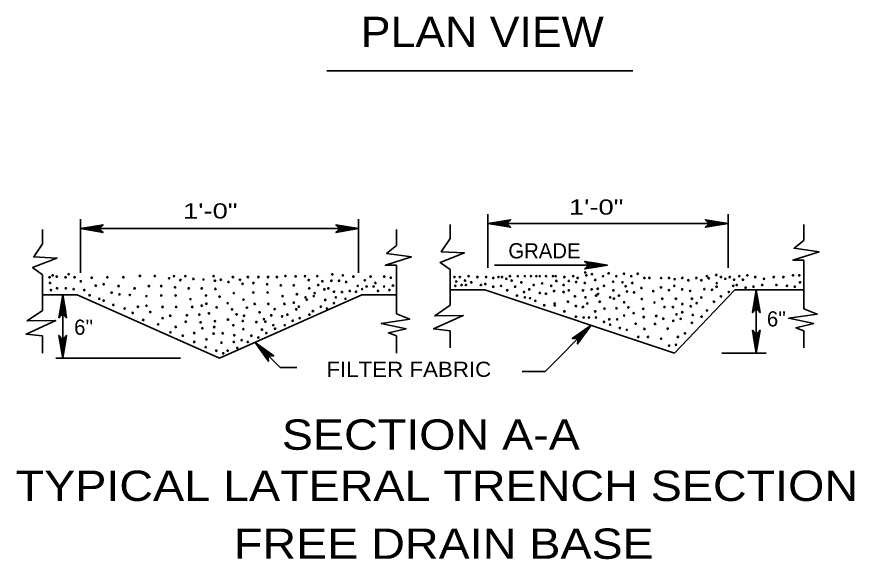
# Model space of a CAD drawing. Extents: x -48732 to -48696.6, y -117659.8 to -117637.8.
# Drawn here: x -48715.46 to -48708.83, y -117648.28 to -117643.99 of the extents above; entities that cross this region are included whole.
import ezdxf

# ---------------------------------------------------------------- set-up
doc = ezdxf.new("R2010")
doc.units = 0
doc.header["$LTSCALE"] = 0.048
doc.layers.add('3', color=7, linetype='Continuous', lineweight=35)

msp = doc.modelspace()

# ---------------------------------------------------------------- linework, layer by layer
at = {"layer": '3'}
for p, q in [((-48713.00633, -117644.41467), (-48710.58575, -117644.41467)), ((-48714.95692, -117646.01342), (-48714.95692, -117645.58742)), ((-48712.75492, -117646.01342), (-48712.75492, -117645.58742)), ((-48711.73225, -117645.97275), (-48711.73225, -117645.54675)), ((-48709.83125, -117645.97275), (-48709.83125, -117645.54675)), ((-48712.03125, -117645.74175), (-48712.03125, -117645.62975)), ((-48711.73225, -117645.62175), (-48709.83125, -117645.62175)), ((-48709.23125, -117645.75575), (-48709.23125, -117645.62975)), ((-48715.25592, -117645.78242), (-48715.25592, -117645.67042)), ((-48714.95692, -117645.66242), (-48712.75492, -117645.66242)), ((-48712.45592, -117645.79642), (-48712.45592, -117645.67042)), ((-48709.23125, -117646.29675), (-48709.23125, -117645.91175)), ((-48712.45592, -117646.33742), (-48712.45592, -117645.95242)), ((-48712.03125, -117646.26875), (-48712.03125, -117645.98675)), ((-48711.68025, -117645.95175), (-48710.78625, -117645.95175)), ((-48715.25592, -117646.30942), (-48715.25592, -117646.02742)), ((-48712.03125, -117646.14675), (-48711.75725, -117646.14675)), ((-48711.75725, -117646.14675), (-48710.25625, -117646.64675)), ((-48710.25625, -117646.64675), (-48709.77925, -117646.14675)), ((-48709.50525, -117646.14675), (-48709.77925, -117646.14675)), ((-48709.63025, -117646.28175), (-48709.60825, -117646.14675)), ((-48709.60825, -117646.14675), (-48709.58525, -117646.28175)), ((-48709.60825, -117646.64675), (-48709.60825, -117646.14675)), ((-48709.23125, -117646.14675), (-48709.50525, -117646.14675)), ((-48715.25592, -117646.18742), (-48714.98192, -117646.18742)), ((-48715.11792, -117646.32242), (-48715.09592, -117646.18742)), ((-48715.09592, -117646.68742), (-48715.09592, -117646.18742)), ((-48715.09592, -117646.18742), (-48715.07292, -117646.32242)), ((-48714.98192, -117646.18742), (-48713.85592, -117646.68742)), ((-48712.72992, -117646.18742), (-48713.85592, -117646.68742)), ((-48712.45592, -117646.18742), (-48712.72992, -117646.18742)), ((-48709.58525, -117646.28175), (-48709.63025, -117646.28175)), ((-48715.07292, -117646.32242), (-48715.11792, -117646.32242)), ((-48710.98125, -117646.47275), (-48710.91625, -117646.42675)), ((-48710.91625, -117646.42675), (-48710.96225, -117646.49175)), ((-48715.25592, -117646.64742), (-48715.25592, -117646.51142)), ((-48712.45592, -117646.64742), (-48712.45592, -117646.51142)), ((-48712.03125, -117646.60675), (-48712.03125, -117646.47075)), ((-48710.96225, -117646.49175), (-48710.98125, -117646.47275)), ((-48709.23125, -117646.60675), (-48709.23125, -117646.47075)), ((-48715.09592, -117646.68742), (-48715.11692, -117646.55942)), ((-48715.11692, -117646.55942), (-48715.07492, -117646.55942)), ((-48715.07492, -117646.55942), (-48715.09592, -117646.68742)), ((-48713.37592, -117646.76142), (-48713.57492, -117646.56442)), ((-48709.60825, -117646.64675), (-48709.62925, -117646.51875)), ((-48709.62925, -117646.51875), (-48709.58725, -117646.51875)), ((-48709.58725, -117646.51875), (-48709.60825, -117646.64675)), ((-48709.88125, -117646.64675), (-48709.53025, -117646.64675)), ((-48715.15192, -117646.68742), (-48714.16492, -117646.68742)), ((-48713.37592, -117646.76142), (-48713.24392, -117646.76142))]:
    msp.add_line(p, q, dxfattribs=at)
for points in [[(-48714.77692, -117645.63242), (-48714.95692, -117645.66242), (-48714.77692, -117645.69242), (-48714.78192, -117645.68842), (-48714.93892, -117645.66242), (-48714.78092, -117645.63642), (-48714.78592, -117645.64042), (-48714.91992, -117645.66242), (-48714.78592, -117645.68442), (-48714.79092, -117645.68142), (-48714.90192, -117645.66242), (-48714.79092, -117645.64342), (-48714.79492, -117645.64742), (-48714.88392, -117645.66242), (-48714.79492, -117645.67742), (-48714.79992, -117645.67342), (-48714.86592, -117645.66242), (-48714.79992, -117645.65142), (-48714.80392, -117645.65542), (-48714.84692, -117645.66242), (-48714.80392, -117645.66942), (-48714.80892, -117645.66542), (-48714.82892, -117645.66242), (-48714.80892, -117645.65942), (-48714.77692, -117645.63242), (-48714.81292, -117645.66242), (-48714.77692, -117645.69242)], [(-48712.93492, -117645.69242), (-48712.75492, -117645.66242), (-48712.93492, -117645.63242), (-48712.92992, -117645.63642), (-48712.77292, -117645.66242), (-48712.93092, -117645.68842), (-48712.92592, -117645.68442), (-48712.79192, -117645.66242), (-48712.92592, -117645.64042), (-48712.92092, -117645.64342), (-48712.80992, -117645.66242), (-48712.92092, -117645.68142), (-48712.91692, -117645.67742), (-48712.82792, -117645.66242), (-48712.91692, -117645.64742), (-48712.91192, -117645.65142), (-48712.84592, -117645.66242), (-48712.91192, -117645.67342), (-48712.90792, -117645.66942), (-48712.86492, -117645.66242), (-48712.90792, -117645.65542), (-48712.90292, -117645.65942), (-48712.88292, -117645.66242), (-48712.90292, -117645.66542), (-48712.93492, -117645.69242), (-48712.89892, -117645.66242), (-48712.93492, -117645.63242)], [(-48711.55225, -117645.59175), (-48711.73225, -117645.62175), (-48711.55225, -117645.65175), (-48711.55725, -117645.64775), (-48711.71425, -117645.62175), (-48711.55625, -117645.59575), (-48711.56125, -117645.59975), (-48711.69525, -117645.62175), (-48711.56125, -117645.64375), (-48711.56625, -117645.64075), (-48711.67725, -117645.62175), (-48711.56625, -117645.60275), (-48711.57025, -117645.60675), (-48711.65925, -117645.62175), (-48711.57025, -117645.63675), (-48711.57525, -117645.63275), (-48711.64125, -117645.62175), (-48711.57525, -117645.61075), (-48711.57925, -117645.61475), (-48711.62225, -117645.62175), (-48711.57925, -117645.62875), (-48711.58425, -117645.62475), (-48711.60425, -117645.62175), (-48711.58425, -117645.61875), (-48711.55225, -117645.59175), (-48711.58825, -117645.62175), (-48711.55225, -117645.65175)], [(-48710.01125, -117645.65175), (-48709.83125, -117645.62175), (-48710.01125, -117645.59175), (-48710.00625, -117645.59575), (-48709.84925, -117645.62175), (-48710.00725, -117645.64775), (-48710.00225, -117645.64375), (-48709.86825, -117645.62175), (-48710.00225, -117645.59975), (-48709.99725, -117645.60275), (-48709.88625, -117645.62175), (-48709.99725, -117645.64075), (-48709.99325, -117645.63675), (-48709.90425, -117645.62175), (-48709.99325, -117645.60675), (-48709.98825, -117645.61075), (-48709.92225, -117645.62175), (-48709.98825, -117645.63275), (-48709.98425, -117645.62875), (-48709.94125, -117645.62175), (-48709.98425, -117645.61475), (-48709.97925, -117645.61875), (-48709.95925, -117645.62175), (-48709.97925, -117645.62475), (-48710.01125, -117645.65175), (-48709.97525, -117645.62175), (-48710.01125, -117645.59175)], [(-48715.25592, -117645.78242), (-48715.32592, -117645.88642), (-48715.14292, -117645.89542), (-48715.33492, -117645.97042), (-48715.25592, -117646.02742)], [(-48712.03125, -117645.74175), (-48712.10125, -117645.84575), (-48711.91825, -117645.85475), (-48712.11025, -117645.92975), (-48712.03125, -117645.98675)], [(-48709.23125, -117645.75575), (-48709.30925, -117645.81775), (-48709.11225, -117645.84575), (-48709.31825, -117645.91175), (-48709.23125, -117645.91175)], [(-48712.45592, -117645.79642), (-48712.53392, -117645.85842), (-48712.33692, -117645.88642), (-48712.54292, -117645.95242), (-48712.45592, -117645.95242)], [(-48710.96625, -117645.98175), (-48710.78625, -117645.95175), (-48710.96625, -117645.92175), (-48710.96125, -117645.92575), (-48710.80425, -117645.95175), (-48710.96225, -117645.97775), (-48710.95725, -117645.97375), (-48710.82325, -117645.95175), (-48710.95725, -117645.92975), (-48710.95225, -117645.93275), (-48710.84125, -117645.95175), (-48710.95225, -117645.97075), (-48710.94825, -117645.96675), (-48710.85925, -117645.95175), (-48710.94825, -117645.93675), (-48710.94325, -117645.94075), (-48710.87725, -117645.95175), (-48710.94325, -117645.96275), (-48710.93925, -117645.95875), (-48710.89625, -117645.95175), (-48710.93925, -117645.94475), (-48710.93425, -117645.94875), (-48710.91425, -117645.95175), (-48710.93425, -117645.95475), (-48710.96625, -117645.98175), (-48710.93025, -117645.95175), (-48710.96625, -117645.92175)], [(-48709.57825, -117646.32675), (-48709.60825, -117646.14675), (-48709.63825, -117646.32675), (-48709.63425, -117646.32175), (-48709.60825, -117646.16475), (-48709.58225, -117646.32275), (-48709.58625, -117646.31775), (-48709.60825, -117646.18375), (-48709.63025, -117646.31775), (-48709.62725, -117646.31275), (-48709.60825, -117646.20175), (-48709.58925, -117646.31275), (-48709.59325, -117646.30875), (-48709.60825, -117646.21975), (-48709.62325, -117646.30875), (-48709.61925, -117646.30375), (-48709.60825, -117646.23775), (-48709.59725, -117646.30375), (-48709.60125, -117646.29975), (-48709.60825, -117646.25675), (-48709.61525, -117646.29975), (-48709.61125, -117646.29475), (-48709.60825, -117646.27475), (-48709.60525, -117646.29475), (-48709.57825, -117646.32675), (-48709.60825, -117646.29075), (-48709.63825, -117646.32675)], [(-48715.06592, -117646.36742), (-48715.09592, -117646.18742), (-48715.12592, -117646.36742), (-48715.12192, -117646.36242), (-48715.09592, -117646.20542), (-48715.06992, -117646.36342), (-48715.07392, -117646.35842), (-48715.09592, -117646.22442), (-48715.11792, -117646.35842), (-48715.11492, -117646.35342), (-48715.09592, -117646.24242), (-48715.07692, -117646.35342), (-48715.08092, -117646.34942), (-48715.09592, -117646.26042), (-48715.11092, -117646.34942), (-48715.10692, -117646.34442), (-48715.09592, -117646.27842), (-48715.08492, -117646.34442), (-48715.08892, -117646.34042), (-48715.09592, -117646.29742), (-48715.10292, -117646.34042), (-48715.09892, -117646.33542), (-48715.09592, -117646.31542), (-48715.09292, -117646.33542), (-48715.06592, -117646.36742), (-48715.09592, -117646.33142), (-48715.12592, -117646.36742)], [(-48715.25592, -117646.30942), (-48715.37792, -117646.39342), (-48715.15192, -117646.38942), (-48715.38692, -117646.49742), (-48715.25592, -117646.51142)], [(-48712.03125, -117646.26875), (-48712.15325, -117646.35275), (-48711.92725, -117646.34875), (-48712.16225, -117646.45675), (-48712.03125, -117646.47075)], [(-48709.23125, -117646.29675), (-48709.12625, -117646.33875), (-48709.35125, -117646.37175), (-48709.15425, -117646.41375), (-48709.29525, -117646.44675), (-48709.23125, -117646.47075)], [(-48712.45592, -117646.33742), (-48712.35092, -117646.37942), (-48712.57592, -117646.41242), (-48712.37892, -117646.45442), (-48712.51992, -117646.48742), (-48712.45592, -117646.51142)], [(-48711.46025, -117646.79375), (-48711.28025, -117646.79375), (-48710.91625, -117646.42675)], [(-48711.02225, -117646.57475), (-48710.91625, -117646.42675), (-48711.06425, -117646.53275), (-48711.05925, -117646.53275), (-48710.92925, -117646.43975), (-48711.02225, -117646.56975), (-48711.02125, -117646.56375), (-48710.94225, -117646.45275), (-48711.05325, -117646.53175), (-48711.04725, -117646.53075), (-48710.95525, -117646.46575), (-48711.02025, -117646.55775), (-48711.02025, -117646.55175), (-48710.96825, -117646.47875), (-48711.04125, -117646.53075), (-48711.03525, -117646.52975), (-48710.98025, -117646.49075), (-48711.01925, -117646.54575), (-48711.01925, -117646.53975), (-48710.99325, -117646.50375), (-48711.02925, -117646.52975), (-48711.02325, -117646.52875), (-48711.00625, -117646.51675), (-48711.01825, -117646.53375), (-48711.02225, -117646.57475), (-48711.01825, -117646.52875), (-48711.06425, -117646.53275)], [(-48715.12592, -117646.50742), (-48715.09592, -117646.68742), (-48715.06592, -117646.50742), (-48715.06992, -117646.51242), (-48715.09592, -117646.66942), (-48715.12192, -117646.51142), (-48715.11792, -117646.51642), (-48715.09592, -117646.65042), (-48715.07392, -117646.51642), (-48715.07692, -117646.52142), (-48715.09592, -117646.63242), (-48715.11492, -117646.52142), (-48715.11092, -117646.52542), (-48715.09592, -117646.61442), (-48715.08092, -117646.52542), (-48715.08492, -117646.53042), (-48715.09592, -117646.59642), (-48715.10692, -117646.53042), (-48715.10292, -117646.53442), (-48715.09592, -117646.57742), (-48715.08892, -117646.53442), (-48715.09292, -117646.53942), (-48715.09592, -117646.55942), (-48715.09892, -117646.53942), (-48715.12592, -117646.50742), (-48715.09592, -117646.54342), (-48715.06592, -117646.50742)], [(-48709.63825, -117646.46675), (-48709.60825, -117646.64675), (-48709.57825, -117646.46675), (-48709.58225, -117646.47175), (-48709.60825, -117646.62875), (-48709.63425, -117646.47075), (-48709.63025, -117646.47575), (-48709.60825, -117646.60975), (-48709.58625, -117646.47575), (-48709.58925, -117646.48075), (-48709.60825, -117646.59175), (-48709.62725, -117646.48075), (-48709.62325, -117646.48475), (-48709.60825, -117646.57375), (-48709.59325, -117646.48475), (-48709.59725, -117646.48975), (-48709.60825, -117646.55575), (-48709.61925, -117646.48975), (-48709.61525, -117646.49375), (-48709.60825, -117646.53675), (-48709.60125, -117646.49375), (-48709.60525, -117646.49875), (-48709.60825, -117646.51875), (-48709.61125, -117646.49875), (-48709.63825, -117646.46675), (-48709.60825, -117646.50275), (-48709.57825, -117646.46675)], [(-48713.42692, -117646.67042), (-48713.57492, -117646.56442), (-48713.46892, -117646.71242), (-48713.46892, -117646.70742), (-48713.56192, -117646.57742), (-48713.43192, -117646.67042), (-48713.43792, -117646.66942), (-48713.54892, -117646.59042), (-48713.46992, -117646.70142), (-48713.47092, -117646.69542), (-48713.53592, -117646.60342), (-48713.44392, -117646.66842), (-48713.44992, -117646.66842), (-48713.52292, -117646.61642), (-48713.47092, -117646.68942), (-48713.47192, -117646.68342), (-48713.51092, -117646.62842), (-48713.45592, -117646.66742), (-48713.46192, -117646.66742), (-48713.49792, -117646.64142), (-48713.47192, -117646.67742), (-48713.47292, -117646.67142), (-48713.48492, -117646.65442), (-48713.46792, -117646.66642), (-48713.42692, -117646.67042), (-48713.47292, -117646.66642), (-48713.46892, -117646.71242)]]:
    msp.add_lwpolyline(points, dxfattribs=at)
msp.add_lwpolyline([(-48710.91025, -117645.97175), (-48710.91025, -117645.93075), (-48710.78625, -117645.95175)], close=True, dxfattribs=at)
for centre in [(-48715.20042, -117646.04692), (-48715.17642, -117646.03192), (-48715.14342, -117646.04192), (-48715.07342, -117646.04692), (-48715.04942, -117646.02292), (-48715.00242, -117646.04692), (-48714.86642, -117646.05092), (-48714.74342, -117646.04692), (-48714.61642, -117646.04692), (-48714.48542, -117646.03692), (-48714.36742, -117646.03692), (-48714.25442, -117646.05592), (-48714.21567, -117646.03892), (-48714.12525, -117646.03892), (-48713.90258, -117646.03892), (-48713.7495, -117646.04583), (-48713.63125, -117646.04583), (-48713.54775, -117646.04583), (-48713.47117, -117646.04583), (-48713.40167, -117646.04583), (-48713.33342, -117646.03692), (-48713.25342, -117646.04092), (-48713.179, -117646.03892), (-48713.08158, -117646.03892), (-48712.96333, -117646.025), (-48712.87983, -117646.03192), (-48712.79642, -117646.04192), (-48712.66042, -117646.04192), (-48712.55242, -117646.04192), (-48712.50042, -117646.05092), (-48711.99617, -117646.04583), (-48711.95442, -117646.04583), (-48711.88483, -117646.03892), (-48711.81525, -117646.04583), (-48711.74575, -117646.04583), (-48711.69008, -117646.05283), (-48711.64833, -117646.04583), (-48711.6205, -117646.04583), (-48711.55783, -117646.03892), (-48711.49525, -117646.03892), (-48711.43958, -117646.03892), (-48711.39083, -117646.03892), (-48711.34908, -117646.03892), (-48711.32133, -117646.03892), (-48711.27258, -117646.03892), (-48711.21692, -117646.03892), (-48711.19608, -117646.03892), (-48711.1265, -117646.04583), (-48711.05692, -117646.03892), (-48711.02208, -117646.05283), (-48710.96158, -117646.00942), (-48710.9525, -117646.03192), (-48710.90892, -117646.02258), (-48710.82033, -117646.03892), (-48710.77717, -117646.016), (-48710.716, -117646.03892), (-48710.65533, -117646.01933), (-48710.59767, -117646.03892), (-48710.54667, -117646.01933), (-48710.49333, -117646.05283), (-48710.45442, -117646.05225), (-48710.36117, -117646.05283), (-48710.2985, -117646.05283), (-48710.19417, -117646.05283), (-48710.08283, -117646.05283), (-48709.99933, -117646.03892), (-48709.98475, -117646.05525), (-48709.92475, -117646.02925), (-48709.888, -117646.04583), (-48709.81842, -117646.04583), (-48709.74192, -117646.03892), (-48709.67925, -117646.03192), (-48709.61667, -117646.04583), (-48709.47058, -117646.04583), (-48709.394, -117646.04583), (-48709.3175, -117646.03192), (-48709.26875, -117646.03192), (-48715.19683, -117646.0925), (-48714.95333, -117646.07858), (-48714.83508, -117646.11342), (-48714.77242, -117646.10292), (-48714.65442, -117646.11692), (-48714.41442, -117646.11692), (-48714.31642, -117646.11692), (-48714.16542, -117646.06992), (-48714.06242, -117646.06092), (-48713.98242, -117646.06492), (-48713.89242, -117646.07492), (-48713.8455, -117646.06675), (-48713.78442, -117646.08392), (-48713.69383, -117646.06675), (-48713.67317, -117646.0995), (-48713.58742, -117646.09292), (-48713.47842, -117646.10292), (-48713.37042, -117646.11192), (-48713.26742, -117646.11192), (-48713.14942, -117646.06992), (-48713.07458, -117646.1085), (-48713.04142, -117646.07892), (-48712.97042, -117646.07492), (-48712.90942, -117646.07492), (-48712.85342, -117646.08392), (-48712.7615, -117646.11542), (-48712.706, -117646.07167), (-48712.69208, -117646.12033), (-48712.63642, -117646.12033), (-48712.6225, -117646.0925), (-48712.553, -117646.12033), (-48712.48342, -117646.11342), (-48711.98925, -117646.11542), (-48711.98225, -117646.08067), (-48711.9405, -117646.1085), (-48711.91267, -117646.07367), (-48711.90575, -117646.1085), (-48711.864, -117646.08758), (-48711.78742, -117646.1085), (-48711.75267, -117646.1015), (-48711.69008, -117646.12242), (-48711.62742, -117646.11542), (-48711.58567, -117646.05975), (-48711.54392, -117646.07367), (-48711.51608, -117646.12242), (-48711.46742, -117646.08758), (-48711.37, -117646.1085), (-48711.30275, -117646.09525), (-48711.23083, -117646.11542), (-48711.18975, -117646.07625), (-48711.13342, -117646.1085), (-48711.09175, -117646.07625), (-48711.034, -117646.08517), (-48710.96492, -117646.09175), (-48710.88258, -117646.06875), (-48710.81342, -117646.11542), (-48710.74092, -117646.08192), (-48710.66725, -117646.08758), (-48710.64217, -117646.11817), (-48710.58942, -117646.09175), (-48710.25675, -117646.11542), (-48710.25375, -117646.06225), (-48710.14575, -117646.07125), (-48710.04275, -117646.07125), (-48709.92283, -117646.12242), (-48709.92075, -117646.09425), (-48709.85325, -117646.05975), (-48709.79058, -117646.11542), (-48709.78367, -117646.06675), (-48709.76275, -117646.1085), (-48709.71408, -117646.06675), (-48709.63058, -117646.12242), (-48709.561, -117646.1085), (-48709.54708, -117646.05975), (-48709.44967, -117646.1085), (-48709.36617, -117646.11542), (-48709.30358, -117646.12242), (-48709.26183, -117646.08758), (-48715.18992, -117646.14825), (-48715.14117, -117646.13425), (-48715.07167, -117646.13425), (-48715.009, -117646.14125), (-48714.9255, -117646.14825), (-48714.88375, -117646.19), (-48714.70983, -117646.16908), (-48714.64725, -117646.183), (-48714.56542, -117646.18792), (-48714.52742, -117646.13592), (-48714.31642, -117646.19192), (-48714.20742, -117646.12692), (-48714.20342, -117646.19192), (-48714.09942, -117646.13592), (-48713.99642, -117646.13592), (-48713.96342, -117646.19192), (-48713.88842, -117646.13992), (-48713.74242, -117646.17292), (-48713.58742, -117646.16792), (-48713.47442, -117646.16792), (-48713.24342, -117646.18192), (-48713.14542, -117646.13492), (-48713.10242, -117646.17292), (-48713.02592, -117646.14333), (-48712.99442, -117646.13592), (-48712.94958, -117646.16217), (-48712.88675, -117646.16417), (-48712.82433, -117646.15517), (-48712.77558, -117646.16217), (-48712.72692, -117646.14125), (-48712.60167, -117646.15517), (-48712.51125, -117646.14825), (-48711.57875, -117646.15025), (-48711.50217, -117646.192), (-48711.4465, -117646.16417), (-48711.40475, -117646.14333), (-48711.32133, -117646.17117), (-48711.27258, -117646.17808), (-48711.20875, -117646.15625), (-48711.13342, -117646.16417), (-48711.09175, -117646.15125), (-48710.97875, -117646.15125), (-48710.91075, -117646.14333), (-48710.876, -117646.192), (-48710.86275, -117646.13792), (-48710.86075, -117646.18025), (-48710.73875, -117646.15125), (-48710.69508, -117646.192), (-48710.63075, -117646.16025), (-48710.57575, -117646.16725), (-48710.51775, -117646.13225), (-48710.42375, -117646.15725), (-48710.36275, -117646.12725), (-48710.29975, -117646.14925), (-48710.19475, -117646.14325), (-48710.13175, -117646.15625), (-48710.01875, -117646.14125), (-48709.95875, -117646.14625), (-48709.82542, -117646.16417), (-48709.69317, -117646.12942), (-48714.80725, -117646.21783), (-48714.77242, -117646.23175), (-48714.43342, -117646.19692), (-48714.08542, -117646.22092), (-48713.95942, -117646.25692), (-48713.85542, -117646.20092), (-48713.79142, -117646.25258), (-48713.66617, -117646.22475), (-48713.57742, -117646.25792), (-48713.46942, -117646.25792), (-48713.35642, -117646.19692), (-48713.34242, -117646.25792), (-48713.26742, -117646.24792), (-48713.17542, -117646.20592), (-48713.16525, -117646.22475), (-48713.10958, -117646.19692), (-48713.01892, -117646.22683), (-48712.94958, -117646.25258), (-48712.9355, -117646.20592), (-48712.85908, -117646.21783), (-48711.43958, -117646.20592), (-48711.39783, -117646.21292), (-48711.35608, -117646.23375), (-48711.203, -117646.25467), (-48711.09867, -117646.24075), (-48711.04375, -117646.19825), (-48710.95975, -117646.20525), (-48710.94475, -117646.25525), (-48710.84675, -117646.24125), (-48710.76467, -117646.20592), (-48710.73475, -117646.21625), (-48710.65375, -117646.24525), (-48710.51417, -117646.21983), (-48710.41375, -117646.24725), (-48710.35275, -117646.21725), (-48710.24475, -117646.21725), (-48710.11775, -117646.21725), (-48710.07975, -117646.25225), (-48710.04275, -117646.20725), (-48709.94367, -117646.24075), (-48709.888, -117646.199), (-48714.69592, -117646.26658), (-48714.6055, -117646.29442), (-48714.50108, -117646.2805), (-48714.43342, -117646.27192), (-48714.40367, -117646.32225), (-48714.30642, -117646.28192), (-48714.19842, -117646.28192), (-48714.07142, -117646.28192), (-48713.99642, -117646.27192), (-48713.87842, -117646.28592), (-48713.75667, -117646.30133), (-48713.63842, -117646.28792), (-48713.41842, -117646.29992), (-48713.24875, -117646.30133), (-48713.22783, -117646.2805), (-48713.1165, -117646.31525), (-48713.05392, -117646.2805), (-48713.00525, -117646.29442), (-48711.2865, -117646.26858), (-48711.203, -117646.26858), (-48711.1265, -117646.31733), (-48711.036, -117646.27558), (-48710.98033, -117646.2825), (-48710.883, -117646.31733), (-48710.80975, -117646.29525), (-48710.71475, -117646.29225), (-48710.62075, -117646.28625), (-48710.50275, -117646.29725), (-48710.33475, -117646.28325), (-48710.26775, -117646.28325), (-48710.19417, -117646.32425), (-48710.19375, -117646.25925), (-48710.12675, -117646.27725), (-48709.99933, -117646.31033), (-48714.54283, -117646.32917), (-48714.45933, -117646.38492), (-48714.30625, -117646.37092), (-48714.24542, -117646.35192), (-48714.11342, -117646.34792), (-48714.01542, -117646.34292), (-48713.93942, -117646.33292), (-48713.78942, -117646.38192), (-48713.72042, -117646.34092), (-48713.66142, -117646.35192), (-48713.53842, -117646.32492), (-48713.50342, -117646.37892), (-48713.44642, -117646.34892), (-48713.36008, -117646.357), (-48713.31833, -117646.34308), (-48713.22092, -117646.37092), (-48713.14433, -117646.34308), (-48711.036, -117646.35908), (-48710.97342, -117646.36608), (-48710.93167, -117646.36608), (-48710.876, -117646.36608), (-48710.77167, -117646.38), (-48710.709, -117646.38), (-48710.65375, -117646.35025), (-48710.57775, -117646.33125), (-48710.49875, -117646.36225), (-48710.39975, -117646.35325), (-48710.34475, -117646.37525), (-48710.23975, -117646.34125), (-48710.20675, -117646.37625), (-48710.11067, -117646.34517), (-48710.04108, -117646.35908), (-48714.34108, -117646.41967), (-48714.20192, -117646.44058), (-48714.12342, -117646.39892), (-48714.00542, -117646.40392), (-48713.99142, -117646.45092), (-48713.89742, -117646.44192), (-48713.89242, -117646.39492), (-48713.74642, -117646.42692), (-48713.67142, -117646.39292), (-48713.56342, -117646.40192), (-48713.49225, -117646.39883), (-48713.42967, -117646.42667), (-48713.41575, -117646.4545), (-48713.33917, -117646.42667), (-48713.27658, -117646.39183), (-48710.81342, -117646.40083), (-48710.76467, -117646.42175), (-48710.68817, -117646.44958), (-48710.56292, -117646.41475), (-48710.49333, -117646.4565), (-48710.40975, -117646.41625), (-48710.30975, -117646.45325), (-48710.26575, -117646.39225), (-48710.11758, -117646.40783), (-48714.24367, -117646.48233), (-48714.14625, -117646.51017), (-48714.05583, -117646.48925), (-48713.90242, -117646.49292), (-48713.83042, -117646.49092), (-48713.73842, -117646.50592), (-48713.66742, -117646.45792), (-48713.60358, -117646.51017), (-48713.52008, -117646.46142), (-48713.48525, -117646.48925), (-48710.6325, -117646.4635), (-48710.542, -117646.51917), (-48710.4655, -117646.51917), (-48710.22892, -117646.51917), (-48710.17325, -117646.49133), (-48714.05583, -117646.55892), (-48713.95842, -117646.538), (-48713.84017, -117646.56583), (-48713.74275, -117646.55892), (-48713.68008, -117646.545), (-48713.63142, -117646.55892), (-48713.54792, -117646.52408), (-48710.36117, -117646.53308), (-48710.2985, -117646.58875), (-48710.24283, -117646.58183), (-48713.96533, -117646.60067), (-48713.88183, -117646.6285), (-48713.82625, -117646.64942), (-48713.79142, -117646.6285), (-48713.71492, -117646.60758)]:
    msp.add_circle(centre, 0.00515, dxfattribs=at)

# ---------------------------------------------------------------- texts
for s, height, width, p in [('PLAN VIEW', 0.24, 1.1, (-48712.738, -117644.22542)), ('1\'-0"', 0.12, 1.35, (-48711.09125, -117645.55175)), ('1\'-0"', 0.12, 1.35, (-48714.14458, -117645.58225)), ('FILTER FABRIC', 0.12, 1.1, (-48713.01017, -117646.83558)), ('SECTION A-A', 0.24, 1.15, (-48713.3625, -117647.41267)), ('TYPICAL LATERAL TRENCH SECTION', 0.24, 1.15, (-48715.46842, -117647.81775)), ('FREE DRAIN BASE', 0.24, 1.15, (-48713.74208, -117648.27575))]:
    msp.add_text(s, height=height, dxfattribs=dict(at, width=width)).set_placement(p)
for s, p in [('GRADE', (-48711.57025, -117645.89775)), ("6''", (-48709.52425, -117646.43675)), ("6''", (-48715.00592, -117646.50242))]:
    msp.add_text(s, height=0.12, dxfattribs=at).set_placement(p)

doc.saveas('drawing.dxf')
